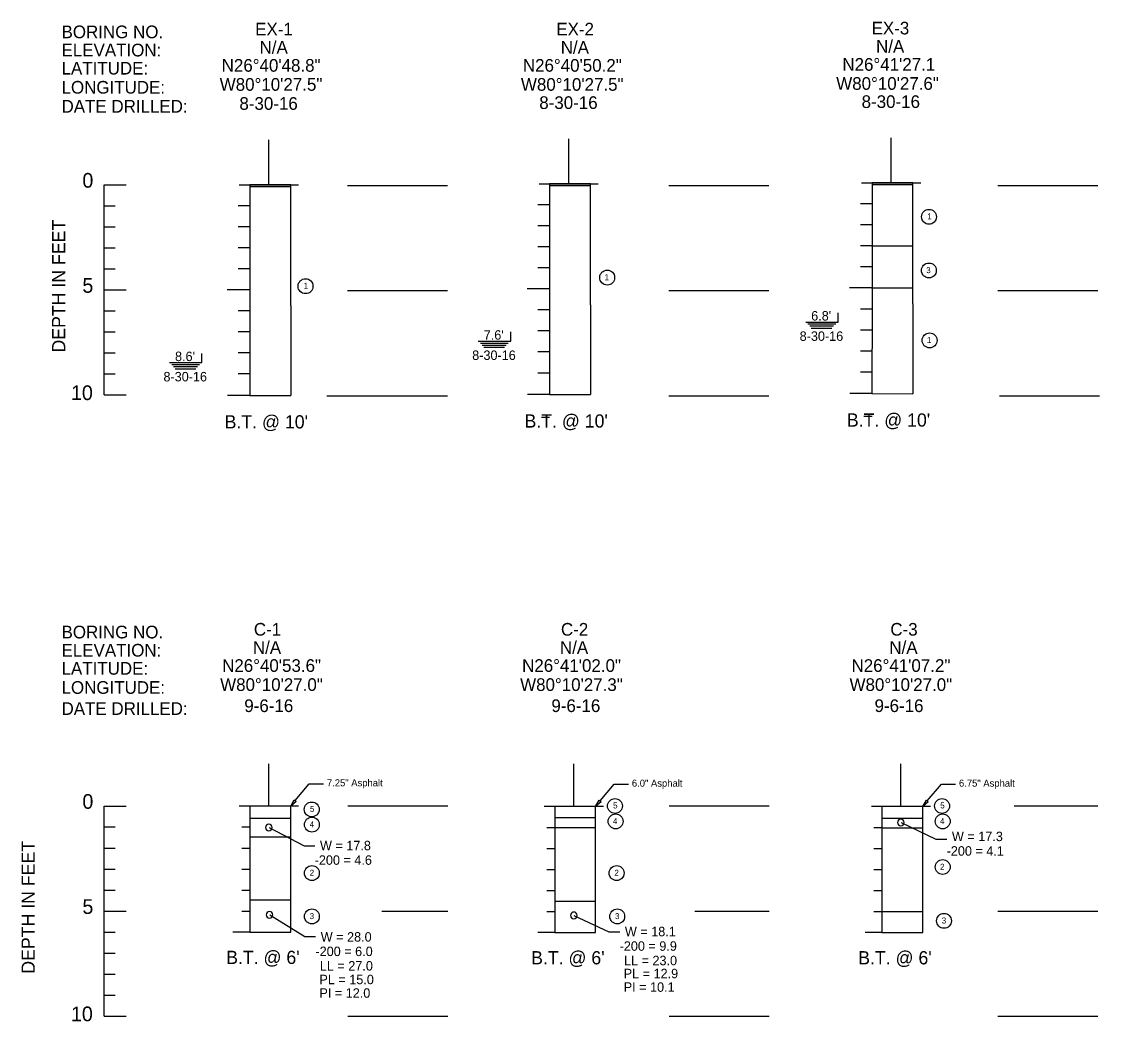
# Model space of a CAD drawing. Extents: x 0 to 331, y -72 to 117.
# Drawn here: x 73.86 to 101.36, y -53.05 to -27.56 of the extents above; entities that cross this region are included whole.
import ezdxf

# ---------------------------------------------------------------- set-up
doc = ezdxf.new("R2010")
doc.units = 0
for name, color, linetype in [('1-BORE', 7, 'Continuous'), ('1-GRID', 7, 'Continuous'), ('1-TEXT', 7, 'Continuous')]:
    doc.layers.add(name, color=color, linetype=linetype)

msp = doc.modelspace()

# ---------------------------------------------------------------- linework, layer by layer
at = {"layer": '1-BORE'}
for p, q in [((79.682, -31.761), (80.727, -31.761)), ((87.333, -31.738), (88.378, -31.738)), ((95.559, -31.714), (96.604, -31.714)), ((95.547, -33.279), (96.604, -33.279)), ((95.559, -33.279), (96.604, -33.279)), ((95.547, -34.351), (96.604, -34.351)), ((95.559, -34.351), (96.604, -34.351)), ((79.682, -34.8), (79.681, -37.089)), ((80.727, -34.8), (80.726, -37.093)), ((87.333, -34.778), (87.333, -37.067)), ((88.378, -34.778), (88.378, -37.071)), ((95.559, -34.753), (95.558, -37.043)), ((96.604, -34.753), (96.603, -37.046)), ((79.681, -37.089), (80.726, -37.093)), ((81.652, -37.097), (82.697, -37.097)), ((87.333, -37.067), (88.378, -37.071)), ((95.558, -37.043), (96.603, -37.046)), ((79.682, -47.869), (80.727, -47.869)), ((80.175, -48.109), (81.067, -48.576)), ((87.462, -47.857), (88.507, -47.857)), ((87.462, -48.106), (88.507, -48.106)), ((87.462, -48.106), (88.507, -48.106)), ((95.809, -47.869), (96.854, -47.869)), ((95.809, -48.119), (96.854, -48.119)), ((95.809, -48.119), (96.854, -48.119)), ((96.299, -47.984), (97.191, -48.402)), ((79.682, -48.348), (80.727, -48.348)), ((79.682, -48.348), (80.727, -48.348)), ((97.191, -48.402), (97.468, -48.402)), ((81.067, -48.576), (81.343, -48.576)), ((79.682, -49.956), (80.727, -49.956)), ((79.682, -49.956), (80.727, -49.956)), ((87.462, -49.986), (88.507, -49.986)), ((87.462, -49.986), (88.507, -49.986)), ((95.809, -50.249), (96.854, -50.249)), ((95.809, -50.249), (96.854, -50.249)), ((80.194, -50.335), (81.086, -50.885)), ((87.955, -50.351), (88.847, -50.772)), ((79.682, -50.775), (79.254, -50.775)), ((79.682, -50.775), (80.727, -50.775)), ((87.462, -50.785), (87.034, -50.785)), ((87.462, -50.785), (88.507, -50.785)), ((88.847, -50.772), (89.124, -50.771)), ((95.809, -50.785), (95.381, -50.785)), ((95.809, -50.785), (96.854, -50.785)), ((81.086, -50.885), (81.363, -50.884))]:
    msp.add_line(p, q, dxfattribs=at)
for points in [[(80.727, -34.8), (80.727, -31.719), (79.682, -31.719), (79.682, -34.8)], [(80.727, -31.761), (80.727, -31.719), (79.682, -31.719), (79.682, -31.761), (80.727, -31.761), (80.727, -31.761)], [(88.378, -34.778), (88.378, -31.697), (87.333, -31.697), (87.333, -34.778)], [(88.378, -31.738), (88.378, -31.697), (87.333, -31.697), (87.333, -31.738), (88.378, -31.738), (88.378, -31.738)], [(96.604, -34.753), (96.604, -31.673), (95.559, -31.673), (95.559, -34.753)], [(96.604, -31.714), (96.604, -31.673), (95.559, -31.673), (95.559, -31.714), (96.604, -31.714), (96.604, -31.714)], [(80.727, -50.775), (80.727, -47.56), (79.682, -47.56), (79.682, -50.775)], [(79.682, -47.56), (79.682, -47.869), (80.727, -47.869), (80.727, -47.56), (79.682, -47.56), (79.682, -47.56)], [(88.507, -50.785), (88.507, -47.57), (87.462, -47.57), (87.462, -50.785)], [(87.462, -47.57), (87.462, -47.857), (88.507, -47.857), (88.507, -47.57), (87.462, -47.57), (87.462, -47.57)], [(96.854, -50.785), (96.854, -47.57), (95.809, -47.57), (95.809, -50.785)], [(95.809, -47.57), (95.809, -47.869), (96.854, -47.869), (96.854, -47.57), (95.809, -47.57), (95.809, -47.57)]]:
    msp.add_lwpolyline(points, dxfattribs=at)
for centre, start, end in [((80.168, -48.107), 0, 180), ((80.168, -48.107), 180, 0), ((96.292, -47.982), 0, 180), ((96.292, -47.982), 180, 0), ((80.188, -50.334), 0, 180), ((87.949, -50.349), 0, 180), ((80.188, -50.334), 180, 0), ((87.949, -50.349), 180, 0)]:
    msp.add_arc(centre, 0.0848, start, end, dxfattribs=at)
at = {"layer": '1-GRID'}
for p, q in [((75.966, -31.72), (76.531, -31.72)), ((75.966, -31.72), (76.531, -31.72)), ((82.175, -31.739), (84.729, -31.739)), ((90.374, -31.739), (92.928, -31.739)), ((98.771, -31.74), (101.324, -31.74)), ((75.966, -32.256), (76.251, -32.256)), ((79.67, -32.254), (79.385, -32.254)), ((87.321, -32.232), (87.036, -32.232)), ((95.547, -32.207), (95.262, -32.207)), ((75.966, -32.792), (76.251, -32.792)), ((79.67, -32.79), (79.385, -32.79)), ((87.321, -32.768), (87.036, -32.768)), ((95.547, -32.743), (95.262, -32.743)), ((75.966, -33.328), (76.251, -33.328)), ((79.67, -33.326), (79.385, -33.326)), ((87.321, -33.304), (87.036, -33.304)), ((95.547, -33.279), (95.262, -33.279)), ((95.547, -33.815), (95.262, -33.815)), ((75.966, -33.864), (76.251, -33.864)), ((79.67, -33.862), (79.385, -33.862)), ((87.321, -33.84), (87.036, -33.84)), ((87.321, -34.376), (86.757, -34.376)), ((95.547, -34.351), (94.982, -34.351)), ((75.966, -34.4), (76.531, -34.4)), ((75.966, -34.4), (76.531, -34.4)), ((79.67, -34.398), (79.105, -34.398)), ((82.175, -34.418), (84.729, -34.418)), ((90.374, -34.418), (92.928, -34.418)), ((98.771, -34.419), (101.324, -34.419)), ((87.321, -34.912), (87.036, -34.912)), ((95.547, -34.887), (95.262, -34.887)), ((75.966, -34.936), (76.251, -34.936)), ((79.67, -34.934), (79.385, -34.934)), ((75.966, -35.472), (76.251, -35.472)), ((79.67, -35.469), (79.385, -35.469)), ((87.321, -35.447), (87.036, -35.447)), ((95.547, -35.423), (95.262, -35.423)), ((75.966, -36.007), (76.251, -36.007)), ((79.67, -36.005), (79.385, -36.005)), ((87.321, -35.983), (87.036, -35.983)), ((95.547, -35.959), (95.262, -35.959)), ((75.966, -36.543), (76.251, -36.543)), ((79.67, -36.541), (79.385, -36.541)), ((87.321, -36.519), (87.036, -36.519)), ((95.547, -36.494), (95.262, -36.494)), ((75.966, -37.079), (76.531, -37.079)), ((79.68, -37.089), (79.115, -37.089)), ((82.175, -37.097), (84.729, -37.097)), ((87.332, -37.067), (86.767, -37.067)), ((90.374, -37.097), (92.928, -37.097)), ((95.557, -37.043), (94.992, -37.043)), ((98.808, -37.097), (101.362, -37.097)), ((87.129, -37.643), (87.334, -37.643)), ((95.354, -37.618), (95.559, -37.618)), ((75.966, -47.56), (76.531, -47.56)), ((75.966, -47.56), (76.531, -47.56)), ((82.183, -47.559), (84.737, -47.559)), ((90.384, -47.559), (92.938, -47.559)), ((99.189, -47.559), (101.325, -47.559)), ((75.966, -48.095), (76.251, -48.095)), ((79.477, -48.095), (79.682, -48.095)), ((87.258, -48.106), (87.462, -48.106)), ((95.604, -48.106), (95.809, -48.106)), ((75.966, -48.631), (76.251, -48.631)), ((79.477, -48.631), (79.682, -48.631)), ((87.258, -48.641), (87.462, -48.641)), ((95.604, -48.641), (95.809, -48.641)), ((75.966, -49.167), (76.251, -49.167)), ((79.477, -49.167), (79.682, -49.167)), ((87.258, -49.177), (87.462, -49.177)), ((95.604, -49.177), (95.809, -49.177)), ((75.966, -49.703), (76.251, -49.703)), ((79.477, -49.703), (79.682, -49.703)), ((87.258, -49.713), (87.462, -49.713)), ((95.604, -49.713), (95.809, -49.713)), ((75.966, -50.239), (76.531, -50.239)), ((75.966, -50.239), (76.531, -50.239)), ((79.477, -50.239), (79.682, -50.239)), ((83.056, -50.238), (84.737, -50.238)), ((87.258, -50.249), (87.462, -50.249)), ((91.036, -50.238), (92.938, -50.238)), ((95.604, -50.249), (95.809, -50.249)), ((98.771, -50.238), (101.325, -50.238)), ((75.966, -50.775), (76.251, -50.775)), ((75.966, -51.311), (76.251, -51.311)), ((75.966, -51.847), (76.251, -51.847)), ((75.966, -52.382), (76.251, -52.382)), ((75.966, -52.918), (76.531, -52.918)), ((82.183, -52.918), (84.737, -52.918)), ((90.384, -52.917), (92.938, -52.917)), ((98.771, -52.918), (101.325, -52.918))]:
    msp.add_line(p, q, dxfattribs=at)
for points in [[(75.966, -34.4), (75.966, -31.72)], [(75.966, -37.079), (75.966, -34.4)], [(75.966, -50.239), (75.966, -47.56)], [(75.966, -52.918), (75.966, -50.239)]]:
    msp.add_lwpolyline(points, dxfattribs=at)
at = {"layer": '1-TEXT'}
for p, q in [((96.038, -30.522), (96.038, -31.673)), ((80.162, -30.569), (80.162, -31.719)), ((87.813, -30.546), (87.813, -31.697)), ((94.695, -35.22), (94.695, -34.984)), ((86.34, -35.708), (86.34, -35.472)), ((93.869, -35.22), (94.695, -35.22)), ((93.923, -35.269), (94.633, -35.269)), ((93.971, -35.318), (94.577, -35.318)), ((94.009, -35.377), (94.534, -35.377)), ((85.514, -35.708), (86.34, -35.708)), ((78.462, -36.254), (78.462, -36.018)), ((85.569, -35.757), (86.278, -35.757)), ((85.616, -35.805), (86.222, -35.805)), ((85.655, -35.864), (86.179, -35.864)), ((77.637, -36.254), (78.462, -36.254)), ((77.691, -36.303), (78.401, -36.303)), ((77.739, -36.352), (78.345, -36.352)), ((77.777, -36.411), (78.302, -36.411)), ((80.162, -46.481), (80.162, -47.55)), ((87.942, -46.481), (87.942, -47.56)), ((96.289, -46.481), (96.289, -47.56)), ((81.201, -46.992), (81.561, -46.992)), ((88.982, -47.002), (89.342, -47.002)), ((97.328, -47.002), (97.688, -47.002))]:
    msp.add_line(p, q, dxfattribs=at)
for points in [[(79.415, -31.719), (80.925, -31.719)], [(87.067, -31.697), (88.576, -31.697)], [(95.292, -31.673), (96.801, -31.673)], [(80.842, -47.421), (81.201, -46.992)], [(88.623, -47.431), (88.982, -47.002)], [(96.969, -47.431), (97.328, -47.002)], [(79.415, -47.557), (80.925, -47.557)], [(87.196, -47.567), (88.705, -47.567)], [(95.543, -47.567), (97.052, -47.567)]]:
    msp.add_lwpolyline(points, dxfattribs=at)
for points in [[(80.865, -47.441), (80.727, -47.56), (80.819, -47.402)], [(88.646, -47.451), (88.507, -47.57), (88.6, -47.412)], [(96.992, -47.451), (96.854, -47.57), (96.946, -47.412)]]:
    msp.add_lwpolyline(points, close=True, dxfattribs=at)
for centre in [(97.014, -32.536), (97.01, -33.904), (88.802, -34.085), (81.105, -34.305), (97.028, -35.688), (81.264, -47.648), (89, -47.559), (97.346, -47.559), (81.267, -48.034), (89.017, -47.952), (97.363, -47.952), (97.363, -49.116), (97.363, -49.116), (81.267, -49.271), (89.042, -49.271), (81.267, -50.376), (89.058, -50.376), (97.396, -50.488)]:
    msp.add_circle(centre, 0.19, dxfattribs=at)

# ---------------------------------------------------------------- texts
at = {"layer": '1-GRID'}
for s, height, p in [('0', 0.375, (75.412, -31.793)), ('5', 0.375, (75.412, -34.473)), ('10', 0.3751, (75.12, -37.209)), ('0', 0.375, (75.412, -47.632)), ('5', 0.375, (75.412, -50.312)), ('10', 0.3751, (75.12, -53.048))]:
    msp.add_text(s, height=height, dxfattribs=at).set_placement(p)
for p in [(74.975, -35.997), (74.197, -51.836)]:
    msp.add_text('DEPTH IN FEET', height=0.3376, rotation=90, dxfattribs=at).set_placement(p)
at = {"layer": '1-TEXT'}
for s, height, p in [('BORING NO.', 0.3231, (74.88, -27.982)), ('EX-1', 0.3231, (79.82, -27.912)), ('EX-2', 0.3231, (87.504, -27.912)), ('EX-3', 0.3231, (95.549, -27.886)), ('N/A', 0.3231, (79.933, -28.376)), ('N/A', 0.3231, (87.617, -28.376)), ('N/A', 0.3231, (95.662, -28.352)), ('ELEVATION:', 0.3231, (74.88, -28.446)), ('LATITUDE:', 0.3231, (74.88, -28.908)), ('N26%%D40\'48.8"', 0.32313, (78.966, -28.836)), ('N26%%D40\'50.2"', 0.32313, (86.651, -28.836)), ("N26%%D41'27.1", 0.32313, (94.803, -28.812)), ('LONGITUDE:', 0.3231, (74.88, -29.395)), ('W80%%D10\'27.5"', 0.32313, (78.916, -29.322)), ('W80%%D10\'27.5"', 0.32313, (86.601, -29.322)), ('W80%%D10\'27.6"', 0.32313, (94.646, -29.298)), ('DATE DRILLED:', 0.32313, (74.88, -29.88)), ('8-30-16', 0.3231, (79.418, -29.808)), ('8-30-16', 0.3231, (87.069, -29.786)), ('8-30-16', 0.3231, (95.294, -29.761)), ('1', 0.152, (96.968, -32.598)), ('3', 0.152, (96.942, -33.972)), ('1', 0.152, (88.734, -34.153)), ('1', 0.152, (81.059, -34.367)), ("  6.8'", 0.2411, (93.828, -35.181)), ("  7.6'", 0.2411, (85.473, -35.669)), ('8-30-16', 0.2411, (93.713, -35.699)), ('1', 0.152, (96.959, -35.756)), ("  8.6'", 0.2411, (77.596, -36.215)), ('8-30-16', 0.2411, (85.358, -36.186)), ('8-30-16', 0.2411, (77.48, -36.733)), ("B.T. @ 10'", 0.3376, (79.042, -37.933)), ("B.T. @ 10'", 0.3376, (86.693, -37.911)), ("B.T. @ 10'", 0.3376, (94.918, -37.886)), ('C-1', 0.3231, (79.787, -43.216)), ('C-2', 0.3231, (87.622, -43.216)), ('C-3', 0.3231, (96.027, -43.216)), ('BORING NO.', 0.3231, (74.88, -43.286)), ('ELEVATION:', 0.3231, (74.88, -43.75)), ('N/A', 0.3231, (79.762, -43.68)), ('N/A', 0.3231, (87.597, -43.68)), ('N/A', 0.3231, (96.002, -43.68)), ('LATITUDE:', 0.3231, (74.88, -44.212)), ('N26%%D40\'53.6"', 0.32313, (78.977, -44.14)), ('N26%%D41\'02.0"', 0.32313, (86.631, -44.14)), ('N26%%D41\'07.2"', 0.32313, (95.036, -44.14)), ('LONGITUDE:', 0.3231, (74.88, -44.699)), ('W80%%D10\'27.0"', 0.32313, (78.927, -44.626)), ('W80%%D10\'27.3"', 0.32313, (86.581, -44.626)), ('W80%%D10\'27.0"', 0.32313, (94.986, -44.626)), ('DATE DRILLED:', 0.32313, (74.88, -45.237)), ('9-6-16', 0.3231, (79.543, -45.164)), ('9-6-16', 0.3231, (87.378, -45.164)), ('9-6-16', 0.3231, (95.624, -45.164)), ('7.25" Asphalt', 0.18, (81.651, -47.058)), ('6.0" Asphalt', 0.18, (89.432, -47.068)), ('6.75" Asphalt', 0.18, (97.778, -47.068)), ('5', 0.152, (81.218, -47.71)), ('5', 0.152, (88.954, -47.622)), ('5', 0.152, (97.3, -47.622)), ('4', 0.152, (81.211, -48.102)), ('4', 0.152, (88.949, -48.02)), ('4', 0.152, (97.295, -48.02)), ('W = 17.3', 0.2411, (97.598, -48.456)), ('W = 17.8', 0.2411, (81.474, -48.689)), ('-200 = 4.1', 0.2411, (97.463, -48.826)), ('-200 = 4.6', 0.2411, (81.338, -49.059)), ('2', 0.152, (81.211, -49.339)), ('2', 0.152, (88.986, -49.339)), ('2', 0.152, (97.295, -49.185)), ('3', 0.152, (81.211, -50.444)), ('3', 0.152, (89.001, -50.444)), ('3', 0.152, (97.339, -50.556)), ('W = 28.0', 0.2411, (81.493, -51.018)), ('W = 18.1', 0.2411, (89.254, -50.881)), ('-200 = 6.0', 0.2411, (81.358, -51.387)), ('-200 = 9.9', 0.2411, (89.119, -51.251)), ("B.T. @ 6'", 0.3376, (79.08, -51.588)), ("B.T. @ 6'", 0.3376, (86.861, -51.598)), ('LL = 23.0', 0.2411, (89.231, -51.62)), ("B.T. @ 6'", 0.3376, (95.207, -51.598)), ('LL = 27.0', 0.2411, (81.47, -51.756)), ('PL = 15.0', 0.2411, (81.459, -52.104)), ('PL = 12.9', 0.2411, (89.223, -51.952)), ('PI = 12.0', 0.2411, (81.459, -52.449)), ('PI = 10.1', 0.2411, (89.223, -52.298))]:
    msp.add_text(s, height=height, dxfattribs=at).set_placement(p)

doc.saveas('drawing.dxf')
